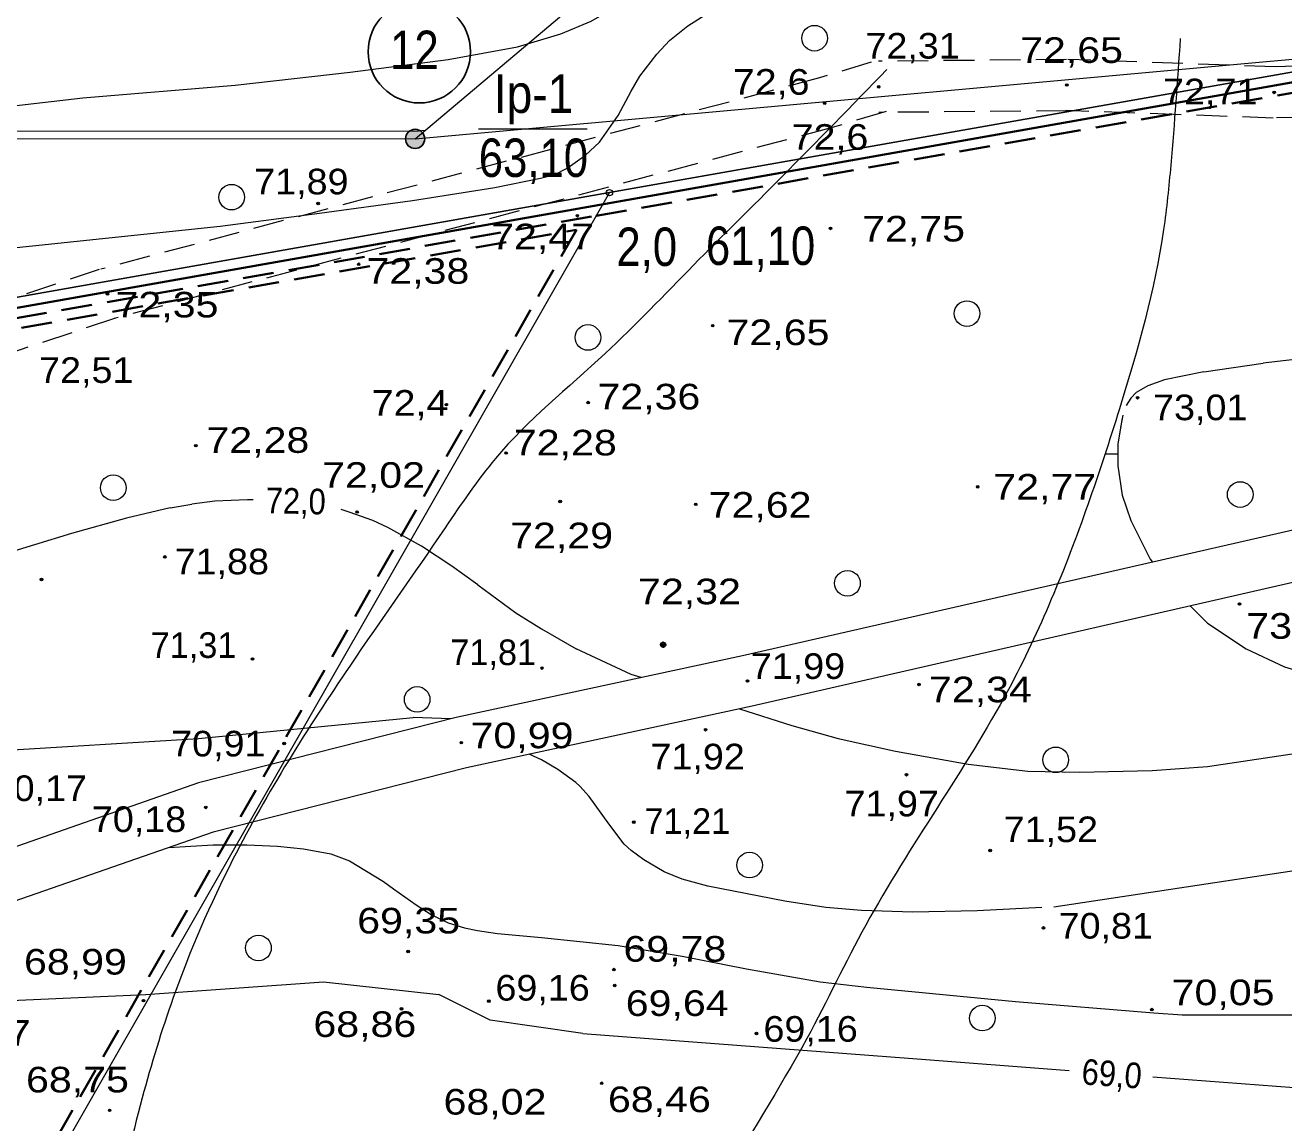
# Model space of a CAD drawing. Extents: x 628176 to 629009, y 6439913 to 6440496.
# Drawn here: x 628433.7 to 628531.9, y 6440341 to 6440426.7 of the extents above; entities that cross this region are included whole.
import ezdxf
from ezdxf.enums import TextEntityAlignment as Align

# ---------------------------------------------------------------- set-up
doc = ezdxf.new("R2010")
doc.units = 0
doc.header["$LTSCALE"] = 0.8
doc.header["$PDMODE"] = 32
doc.header["$PDSIZE"] = 0.4
doc.linetypes.add('MEDIUM_DASHED', pattern=[4.5, 3, -1.5])
for name, color, linetype, lineweight in [('1', 7, 'Continuous', 13), ('10', 7, 'Continuous', 25), ('11', 7, 'Continuous', 13), ('12', 7, 'Continuous', 13), ('14', 7, 'Continuous', 25), ('16', 7, 'Continuous', 13), ('21', 7, 'MEDIUM_DASHED', 35), ('3', 7, 'Continuous', 13), ('6', 7, 'Continuous', 13)]:
    doc.layers.add(name, color=color, linetype=linetype, lineweight=lineweight)

msp = doc.modelspace()

# ---------------------------------------------------------------- hatches: boundary and pattern name
at = {"layer": '1'}
for points in [[(628500.4249, 6440421.8643, 1), (628500.2249, 6440421.8643, 1)], [(628515.1101, 6440422.0044, 1), (628514.9101, 6440422.0044, 1)], [(628531.2948, 6440421.4295, 1), (628531.0948, 6440421.4295, 1)], [(628496.21, 6440420.5937, 1), (628496.01, 6440420.5937, 1)], [(628456.6647, 6440412.7535, 1), (628456.4647, 6440412.7535, 1)], [(628476.9054, 6440411.8006, 1), (628476.7054, 6440411.8006, 1)], [(628496.667, 6440410.8141, 1), (628496.467, 6440410.8141, 1)], [(628459.8357, 6440408.0127, 1), (628459.6357, 6440408.0127, 1)], [(628440.2222, 6440405.7018, 1), (628440.0222, 6440405.7018, 1)], [(628487.466, 6440403.222, 1), (628487.266, 6440403.222, 1)], [(628520.6333, 6440397.5917, 1), (628520.4333, 6440397.5917, 1)], [(628466.6814, 6440397.0508, 1), (628466.4814, 6440397.0508, 1)], [(628477.7532, 6440397.2147, 1), (628477.5532, 6440397.2147, 1)], [(628447.1216, 6440393.8483, 1), (628446.9216, 6440393.8483, 1)], [(628471.3414, 6440393.2829, 1), (628471.1414, 6440393.2829, 1)], [(628508.1525, 6440390.6403, 1), (628507.9525, 6440390.6403, 1)], [(628459.7097, 6440388.6751, 1), (628459.5097, 6440388.6751, 1)], [(628475.5631, 6440389.4925, 1), (628475.3631, 6440389.4925, 1)], [(628486.1441, 6440389.274, 1), (628485.9441, 6440389.274, 1)], [(628444.6993, 6440385.166, 1), (628444.4993, 6440385.166, 1)], [(628435.0827, 6440383.4025, 1), (628434.8827, 6440383.4025, 1)], [(628528.5824, 6440381.489, 1), (628528.3824, 6440381.489, 1)], [(628483.6015, 6440378.3066, 1), (628483.4015, 6440378.3066, 1)], [(628451.5455, 6440377.1994, 1), (628451.3455, 6440377.1994, 1)], [(628474.1418, 6440376.4876, 1), (628473.9418, 6440376.4876, 1)], [(628490.1794, 6440375.4815, 1), (628489.9794, 6440375.4815, 1)], [(628503.5727, 6440375.2012, 1), (628503.3727, 6440375.2012, 1)], [(628486.9129, 6440371.6733, 1), (628486.7129, 6440371.6733, 1)], [(628454.0143, 6440370.5999, 1), (628453.8143, 6440370.5999, 1)], [(628467.8444, 6440370.6674, 1), (628467.6444, 6440370.6674, 1)], [(628502.6009, 6440368.1626, 1), (628502.4009, 6440368.1626, 1)], [(628447.8985, 6440365.6109, 1), (628447.6985, 6440365.6109, 1)], [(628481.306, 6440364.4551, 1), (628481.106, 6440364.4551, 1)], [(628509.1292, 6440362.2436, 1), (628508.9292, 6440362.2436, 1)], [(628513.29, 6440356.2017, 1), (628513.09, 6440356.2017, 1)], [(628463.7022, 6440354.3617, 1), (628463.5022, 6440354.3617, 1)], [(628479.757, 6440352.9509, 1), (628479.557, 6440352.9509, 1)], [(628479.8173, 6440351.7043, 1), (628479.6173, 6440351.7043, 1)], [(628443.0391, 6440350.5246, 1), (628442.8391, 6440350.5246, 1)], [(628469.9998, 6440350.4858, 1), (628469.7998, 6440350.4858, 1)], [(628463.1803, 6440349.8914, 1), (628462.9803, 6440349.8914, 1)], [(628521.7458, 6440349.8289, 1), (628521.5458, 6440349.8289, 1)], [(628490.8812, 6440347.9582, 1), (628490.6812, 6440347.9582, 1)], [(628478.8054, 6440344.0765, 1), (628478.6054, 6440344.0765, 1)], [(628440.3982, 6440341.961, 1), (628440.1982, 6440341.961, 1)]]:
    msp.add_hatch(color=256, dxfattribs=at).paths.add_polyline_path(points)
at = {"layer": '10'}
msp.add_hatch(color=256, dxfattribs=at).paths.add_polyline_path([(628464.89, 6440417.8, 1), (628463.39, 6440417.8, 1)])

# ---------------------------------------------------------------- linework, layer by layer
at = {"layer": '1', "linetype": 'MEDIUM_DASHED'}
for p, q in [((628499.75, 6440423.78), (628495.53, 6440422.51)), ((628514.99, 6440424), (628500.31, 6440423.86)), ((628531.27, 6440423.43), (628515.08, 6440424)), ((628544.47, 6440423.76), (628531.15, 6440423.43)), ((628495.6, 6440422.53), (628439.61, 6440407.63)), ((628500.9, 6440419.95), (628496.69, 6440418.68)), ((628515.03, 6440420), (628500.34, 6440419.86)), ((628531.12, 6440419.43), (628514.94, 6440420.01)), ((628544.56, 6440419.76), (628531.24, 6440419.43)), ((628496.62, 6440418.66), (628440.64, 6440403.77)), ((628439.49, 6440407.6), (628391.01, 6440391.47)), ((628440.75, 6440403.8), (628392.27, 6440387.68))]:
    msp.add_line(p, q, dxfattribs=at)
at = {"layer": '1'}
for p, q in [((628544.93, 6440390.06), (628489.7, 6440377.44)), ((628545.69, 6440386.14), (628490.46, 6440373.52)), ((628483.5, 6440378.31), (628483.25, 6440378.31)), ((628483.5, 6440378.31), (628483.5, 6440378.56)), ((628483.5, 6440378.32), (628483.5, 6440378.06)), ((628483.5, 6440378.31), (628483.75, 6440378.31)), ((628489.7, 6440377.44), (628467.34, 6440372.63)), ((628490.46, 6440373.52), (628468.15, 6440368.71)), ((628467.34, 6440372.63), (628447.23, 6440367.53)), ((628468.15, 6440368.71), (628448.37, 6440363.69)), ((628447.23, 6440367.53), (628425.19, 6440359.83)), ((628448.37, 6440363.69), (628426.81, 6440356.17))]:
    msp.add_line(p, q, dxfattribs=at)
for centre, radius in [((628495.3193, 6440425.662), 1), ((628500.3249, 6440421.8643), 0.1), ((628515.0101, 6440422.0044), 0.1), ((628531.1948, 6440421.4295), 0.1), ((628496.11, 6440420.5937), 0.1), ((628449.8188, 6440413.2528), 1), ((628456.5647, 6440412.7535), 0.1), ((628476.8054, 6440411.8006), 0.1), ((628496.567, 6440410.8141), 0.1), ((628459.7357, 6440408.0127), 0.1), ((628440.1222, 6440405.7018), 0.1), ((628507.217, 6440404.165), 1), ((628477.6286, 6440402.299), 1), ((628487.366, 6440403.222), 0.1), ((628520.5333, 6440397.5917), 0.1), ((628466.5814, 6440397.0508), 0.1), ((628477.6532, 6440397.2147), 0.1), ((628447.0216, 6440393.8483), 0.1), ((628471.2414, 6440393.2829), 0.1), ((628440.5765, 6440390.5703), 1), ((628508.0525, 6440390.6403), 0.1), ((628528.542, 6440390.0372), 1), ((628459.6097, 6440388.6751), 0.1), ((628475.4631, 6440389.4925), 0.1), ((628486.0441, 6440389.274), 0.1), ((628444.5993, 6440385.166), 0.1), ((628497.8873, 6440383.1066), 1), ((628434.9827, 6440383.4025), 0.1), ((628528.4824, 6440381.489), 0.1), ((628483.5015, 6440378.3066), 0.1), ((628451.4455, 6440377.1994), 0.1), ((628474.0418, 6440376.4876), 0.1), ((628464.3005, 6440374.0435), 1), ((628490.0794, 6440375.4815), 0.1), ((628503.4727, 6440375.2012), 0.1), ((628486.8129, 6440371.6733), 0.1), ((628453.9143, 6440370.5999), 0.1), ((628467.7444, 6440370.6674), 0.1), ((628514.1421, 6440369.3249), 1), ((628502.5009, 6440368.1626), 0.1), ((628447.7985, 6440365.6109), 0.1), ((628481.206, 6440364.4551), 0.1), ((628509.0292, 6440362.2436), 0.1), ((628490.2458, 6440361.1106), 1), ((628451.9122, 6440354.6387), 1), ((628513.19, 6440356.2017), 0.1), ((628463.6022, 6440354.3617), 0.1), ((628479.657, 6440352.9509), 0.1), ((628479.7173, 6440351.7043), 0.1), ((628442.9391, 6440350.5246), 0.1), ((628469.8998, 6440350.4858), 0.1), ((628463.0803, 6440349.8914), 0.1), ((628508.4169, 6440349.1625), 1), ((628521.6458, 6440349.8289), 0.1), ((628490.7812, 6440347.9582), 0.1), ((628478.7054, 6440344.0765), 0.1), ((628440.2982, 6440341.961), 0.1)]:
    msp.add_circle(centre, radius, dxfattribs=at)
at = {"layer": '10'}
for centre, radius in [((628464.4704, 6440424.6071), 4), ((628464.14, 6440417.8), 0.75)]:
    msp.add_circle(centre, radius, dxfattribs=at)
at = {"layer": '11'}
for points in [[(628393.19, 6440398.39), (628410.48, 6440417.82), (628464.14, 6440417.8), (628544.36, 6440425.1), (628575.19, 6440427.91), (628595.11, 6440426.87)], [(628393.19, 6440398.39), (628479.31, 6440413.61), (628544.36, 6440425.1)], [(628479.31, 6440413.61), (628403.76, 6440281.52), (628439.01, 6440242.62), (628472.21, 6440157.1)]]:
    msp.add_lwpolyline(points, dxfattribs=at)
msp.add_point((628483.5, 6440378.31), dxfattribs=at)
at = {"layer": '12'}
msp.add_line((628469.09, 6440418.59), (628477.58, 6440418.59), dxfattribs=at)
msp.add_circle((628479.3057, 6440413.6063), 0.25, dxfattribs=at)
at = {"layer": '14'}
msp.add_lwpolyline([(628393.19, 6440398.39), (628479.31, 6440413.61), (628544.36, 6440425.1)], dxfattribs=at)
at = {"layer": '16'}
for points in [[(628523.86, 6440425.63), (628523.12, 6440415.76), (628522.56, 6440410.73), (628519.12, 6440396.74), (628513.8, 6440381.86), (628510.45, 6440374.81), (628499.31, 6440356.42), (628494.72, 6440347.58), (628488, 6440335.91), (628479.91, 6440315.37), (628477.03, 6440304.26), (628475.97, 6440294.36), (628477.03, 6440283.22), (628480.57, 6440271.2), (628486.05, 6440256.7), (628486.58, 6440255.49)], [(628500.95, 6440423.21), (628492.76, 6440414.83), (628485.87, 6440407.94), (628478.97, 6440401.05), (628470.41, 6440392.85), (628466.49, 6440387.45), (628459.04, 6440376.65), (628449.92, 6440361.56), (628445.26, 6440350.76), (628442.84, 6440342.93), (628439.11, 6440323.75), (628438.18, 6440304.38), (628440.79, 6440289.66), (628442.84, 6440282.59), (628446.19, 6440272.53), (628459.6, 6440244.4), (628464.91, 6440235.24)]]:
    msp.add_spline(points, degree=3, dxfattribs=at)
at = {"layer": '21'}
for p, q in [((628478.27, 6440411.8), (628544.61, 6440423.52)), ((628394.01, 6440396.91), (628478.27, 6440411.8)), ((628394.43, 6440396.17), (628476.73, 6440410.71))]:
    msp.add_line(p, q, dxfattribs=at)
at = {"layer": '21', "linetype": 'Continuous', "lineweight": 40}
msp.add_lwpolyline([(628393.6, 6440397.65), (628479.44, 6440412.82), (628544.47, 6440424.31)], dxfattribs=at)
at = {"layer": '21'}
msp.add_lwpolyline([(628476.73, 6440410.71), (628402.77, 6440281.42), (628438.32, 6440242.19), (628470.2, 6440160.05)], dxfattribs=at)
at = {"layer": '3'}
for p, q in [((628448.92, 6440411), (628456.69, 6440412)), ((628429.84, 6440409), (628448.92, 6440411)), ((628525.7, 6440399.62), (628530.34, 6440400.3)), ((628519.37, 6440396.24), (628519.21, 6440395.26)), ((628518, 6440393.22), (628519, 6440393.22)), ((628445.01, 6440389), (628441.6, 6440388.2)), ((628445.01, 6440389), (628446.72, 6440389.29)), ((628451.49, 6440389.61), (628451.05, 6440389.62)), ((628459, 6440388.67), (628458.36, 6440388.87)), ((628441.6, 6440388.2), (628437.31, 6440387)), ((628437.31, 6440387), (628429.98, 6440384.75)), ((628466.9, 6440372.52), (628464, 6440372.63)), ((628476.68, 6440367.55), (628475.27, 6440368.56)), ((628514, 6440357.84), (628552, 6440363.59)), ((628444.88, 6440362.48), (628448.37, 6440362.7)), ((628482, 6440361.51), (628481, 6440362.26)), ((628513.07, 6440357.79), (628508, 6440357.53)), ((628470, 6440349), (628466, 6440351)), ((628477.22, 6440347.96), (628470, 6440349)), ((628477.22, 6440347.96), (628503, 6440346)), ((628503, 6440346), (628515.19, 6440345.07)), ((628521.72, 6440344.58), (628542.5, 6440343))]:
    msp.add_line(p, q, dxfattribs=at)
for points in [[(628422, 6440418.57), (628429.42, 6440420), (628438.21, 6440421), (628450.1, 6440422), (628459.07, 6440423), (628466.71, 6440424), (628472.14, 6440425), (628475.51, 6440426), (628477.87, 6440427), (628479.64, 6440428), (628483.9, 6440431), (628486.91, 6440433), (628490.26, 6440435), (628497.84, 6440439), (628499.78, 6440440), (628501.87, 6440441), (628506.4, 6440443), (628526.88, 6440451), (628533.59, 6440454), (628545.23, 6440460), (628547.31, 6440461)], [(628456.69, 6440412), (628463.93, 6440413), (628470.35, 6440414), (628473.93, 6440414.73), (628475, 6440415), (628476, 6440415.51), (628477.45, 6440416.53), (628478.52, 6440417.54), (628480, 6440419.63), (628481, 6440421.53), (628481.69, 6440422.69), (628483, 6440424.41), (628484, 6440425.48), (628485.43, 6440426.63), (628487, 6440427.61), (628488.32, 6440428.29), (628489.76, 6440428.94), (628491.16, 6440429.47), (628492.32, 6440429.87), (628493.16, 6440430.12), (628494.23, 6440430.38), (628495.46, 6440430.64), (628499.35, 6440431.22), (628502.32, 6440431.36)], [(628546.67, 6440402), (628536.41, 6440401), (628530.34, 6440400.3)], [(628525.7, 6440399.62), (628522.64, 6440399), (628521.34, 6440398.52), (628520.43, 6440398), (628520, 6440397.55), (628519.63, 6440397)], [(628519.33, 6440396), (628519, 6440394), (628519, 6440392.29), (628519.33, 6440390), (628520, 6440388), (628521.51, 6440385), (628521.69, 6440384.75)], [(628451.05, 6440389.62), (628448.52, 6440389.51), (628446.72, 6440389.29)], [(628469.04, 6440383), (628467, 6440384.45), (628464.64, 6440386), (628462, 6440387.46), (628460.84, 6440388), (628459, 6440388.67)], [(628469.04, 6440383), (628472, 6440380.8), (628474, 6440379.56), (628476.71, 6440378)], [(628524.67, 6440381.33), (628526, 6440380), (628529, 6440378), (628532, 6440376.58), (628534, 6440376), (628537, 6440375.54), (628539, 6440375.54), (628541, 6440375.77), (628543.42, 6440376.37), (628545.01, 6440377), (628546.88, 6440378)], [(628481.78, 6440375.74), (628481, 6440376), (628476.71, 6440378)], [(628489.46, 6440373.3), (628493.55, 6440372), (628497.15, 6440371), (628501.63, 6440370), (628507.31, 6440369), (628511.97, 6440368.43), (628516, 6440368.36), (628521.67, 6440368.48), (628526, 6440368.81), (628552.26, 6440372.74), (628556, 6440372.85), (628564.33, 6440372.65), (628570, 6440372.36), (628576.16, 6440371.82), (628580, 6440371.37), (628582.3, 6440371), (628585, 6440370.41), (628588, 6440369.55)], [(628431, 6440370), (628447.23, 6440371), (628464, 6440372.63)], [(628475.27, 6440368.56), (628474, 6440369.33), (628473.03, 6440369.76)], [(628476.68, 6440367.55), (628477, 6440367.26), (628477.72, 6440366.47)], [(628481, 6440362.26), (628480.47, 6440362.74), (628479.26, 6440364.32), (628477.72, 6440366.47)], [(628448.37, 6440362.7), (628451, 6440362.7), (628453.4, 6440362.58), (628455.42, 6440362.37), (628457.56, 6440362), (628459.03, 6440361.44), (628461.68, 6440359.83), (628462.46, 6440359.26), (628464.23, 6440358), (628465.39, 6440357.26), (628466.71, 6440356.61), (628468, 6440356.21), (628469, 6440356), (628470.57, 6440355.76), (628474, 6440355.45), (628480, 6440354.83), (628484.99, 6440354), (628490, 6440353), (628495.75, 6440352), (628499.4, 6440351.58), (628511, 6440350.45), (628521.81, 6440349.57), (628524, 6440349.41)], [(628487, 6440359.45), (628484.99, 6440360), (628483.58, 6440360.59), (628482, 6440361.51)], [(628508, 6440357.53), (628503, 6440357.44), (628498.98, 6440357.56), (628496.19, 6440357.79), (628493, 6440358.28), (628487, 6440359.45)], [(628421.56, 6440346.2), (628423, 6440347.43), (628424.61, 6440348.51), (628427, 6440349.45), (628429.65, 6440350.22), (628432, 6440350.52), (628443.09, 6440351), (628457, 6440352), (628466, 6440351)], [(628524, 6440349.41), (628546, 6440349.41), (628552, 6440350), (628557.22, 6440352)]]:
    msp.add_lwpolyline(points, dxfattribs=at)
at = {"layer": '6'}
msp.add_line((628464.14, 6440417.8), (628528.94, 6440472.45), dxfattribs=at)
msp.add_lwpolyline([(628410.58, 6440418.42), (628464.11, 6440418.4), (628464.94, 6440418.48)], dxfattribs=at)

# ---------------------------------------------------------------- texts
at = {"layer": '1'}
for s, width, p in [('72,31', 1.1, (628499.29, 6440424.07)), ('72,65', 1.2, (628511.36, 6440423.73)), ('72,6', 1.15, (628488.94, 6440421.25)), ('72,71', 1.1, (628522.52, 6440420.5)), ('72,6', 1.15, (628493.53, 6440416.95)), ('71,89', 1.1, (628451.58, 6440413.47)), ('72,75', 1.2, (628499.03, 6440409.79)), ('72,47', 1.2, (628470.07, 6440409.18)), ('72,38', 1.2, (628460.34, 6440406.49)), ('72,35', 1.2, (628440.76, 6440403.86)), ('72,65', 1.2, (628488.45, 6440401.7)), ('72,51', 1.1, (628434.79, 6440398.75)), ('72,36', 1.2, (628478.37, 6440396.68)), ('72,4', 1.15, (628460.75, 6440396.19)), ('73,01', 1.1, (628521.74, 6440395.84)), ('72,28', 1.2, (628447.85, 6440393.29)), ('72,28', 1.2, (628471.85, 6440393.09)), ('72,02', 1.2, (628456.88, 6440390.56)), ('72,77', 1.2, (628509.27, 6440389.64)), ('72,62', 1.2, (628487.05, 6440388.23)), ('72,29', 1.2, (628471.56, 6440385.84)), ('71,88', 1.1, (628445.37, 6440383.81)), ('72,32', 1.2, (628481.54, 6440381.47)), ('73,06', 1.2, (628529.02, 6440378.78)), ('71,99', 1.1, (628490.34, 6440375.64)), ('72,34', 1.2, (628504.25, 6440373.82)), ('70,99', 1.2, (628468.47, 6440370.23)), ('70,91', 1.1, (628445.1, 6440369.59)), ('71,92', 1.1, (628482.51, 6440368.58)), ('70,17', 1.1, (628431.17, 6440366.11)), ('71,97', 1.1, (628497.66, 6440364.91)), ('70,18', 1.1, (628438.91, 6440363.69)), ('71,52', 1.1, (628510.08, 6440362.9)), ('69,35', 1.2, (628459.62, 6440355.77)), ('70,81', 1.1, (628514.37, 6440355.37)), ('69,78', 1.2, (628480.4, 6440353.57)), ('68,99', 1.2, (628433.61, 6440352.56)), ('69,16', 1.1, (628470.41, 6440350.53)), ('70,05', 1.2, (628523.19, 6440350.17)), ('69,64', 1.2, (628480.58, 6440349.33)), ('68,86', 1.2, (628456.2, 6440347.69)), ('69,07', 1.2, (628426.11, 6440347.01)), ('69,16', 1.1, (628491.33, 6440347.32)), ('68,75', 1.2, (628433.77, 6440343.36)), ('68,02', 1.2, (628466.36, 6440341.63)), ('68,46', 1.2, (628479.19, 6440341.82))]:
    msp.add_text(s, height=2, dxfattribs=dict(at, width=width)).set_placement(p)
for s, p in [('71,31', (628443.5, 6440377.28)), ('71,81', (628466.89, 6440376.72)), ('71,21', (628482.04, 6440363.54))]:
    msp.add_text(s, height=2, dxfattribs=at).set_placement(p)
at = {"layer": '10', "width": 0.85}
msp.add_text('12', height=3, dxfattribs=at).set_placement((628464.085, 6440423.25), align=Align.CENTER)
at = {"layer": '12'}
for s, width, p in [('Ip-1', 0.9, (628473.385, 6440419.83)), ('63,10', 0.85, (628473.375, 6440414.83)), ('2,0', 0.85, (628482.22, 6440407.88)), ('61,10', 0.85, (628491.105, 6440407.96))]:
    msp.add_text(s, height=3, dxfattribs=dict(at, width=width)).set_placement(p, align=Align.CENTER)
at = {"layer": '3', "width": 0.9}
for s, rotation, p in [('72,0', 358.568, (628452.46, 6440388.59)), ('69,0', 355.657, (628516.11, 6440344))]:
    msp.add_text(s, height=2, rotation=rotation, dxfattribs=at).set_placement(p)

doc.saveas('drawing.dxf')
